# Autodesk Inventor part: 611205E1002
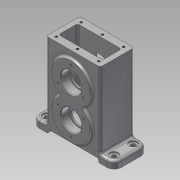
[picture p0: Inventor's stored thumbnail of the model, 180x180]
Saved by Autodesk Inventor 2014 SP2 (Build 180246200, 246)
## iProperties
Created: 2021-12
Part Number: 611205E1002
Material: 강철
Document SubType Name: Modeling
Designer: 거성
Density: 7.85 g/cm^3
Appearance: 강철
Mass: 1730.84 g
Surface Area: 577.617 cm^2
Volume: 220.489 cm^3
Author: 거성
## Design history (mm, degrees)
sketch "스케치1"
  geometry: L1 (-56, -5)-(-35, -5); L2 (-35, -5)-(-35, 0); L3 (-35, 0)-(35, 0); L4 (35, 0)-(35, -5); L5 (35, -5)-(56, -5); L6 (-56, -5)-(-56, 5); L7 (-56, 5)-(-37, 5); L8 (-37, 5)-(-37, 109); L9 (-37, 109)-(37, 109); L10 (37, 109)-(37, 5); L11 (37, 5)-(56, 5); L12 (56, 5)-(56, -5); 3 further points
  constraints: 24 end point, 6 parallel, 3 perpendicular, 2 collinear, 2 midpoint, 1 coincident, 1 horizontal, 1 horizontal alignment, 1 vertical alignment
  dimensions: "d0" = 112 distance between parallel lines of L12 L6; "d1" = 70 distance of L2.end L3.end; "d2" = 10 distance between parallel lines of L1 L7; "d3" = 10 distance between parallel lines of L11 L5; "d4" = 114 distance between parallel lines of L9 L5; "d5" = 5 distance of L1.end L2.end; "d6" = 21 distance of L1.start L1.end; "d7" = 74 distance between parallel lines of L10 L8
extrude "돌출1" new body sketch "스케치1" stored distance "d8" = 46; taper "d9" = 0 deg
sketch "스케치2"
  geometry: L1 (109, -23)-(0, -23) reference; L2 (0, -23)-(0, 23) reference; L3 (0, 23)-(109, 23) reference; L4 (109, 23)-(109, -23) reference; L5 (8, 13)-(109, 13); L6 (109, 13)-(109, -13); L7 (109, -13)-(8, -13); L8 (8, -13)-(8, 13); 3 further points
  constraints: 8 end point, 2 midpoint, 2 parallel, 1 coincident, 1 horizontal, 1 perpendicular
  dimensions: "d10" = 26 distance between parallel lines of L5 L7; "d11" = 10 distance between parallel lines of L1 L7; "d12" = 8 distance between parallel lines of L2 L8
extrude "돌출2" cut sketch "스케치2" stored distance "d13" = 60; taper "d14" = 0 deg
sketch "스케치3"
  geometry: L1 (-35, 0)-(35, 0) reference; L2 (35, -5)-(56, -5) reference; C1 r 26 at (0, 74); C2 r 26 at (0, 29); 4 further points
  constraints: 3 midpoint, 2 centre point, 2 vertical alignment
  dimensions: "d15" = 34 distance from line of C2.centre L2; "d16" = 79 distance from line of C1.centre L2; "d17" = 52 diameter of C1; "d18" = 52 diameter of C2
extrude "돌출3" join sketch "스케치3" distance "d19" = 3; taper "d20" = 0 deg
sketch "스케치4"
  geometry: C1 r 12 at (0, 74); C2 r 14 at (0, 74); C3 r 12 at (0, 29); C4 r 14 at (0, 29); A1 r 26 centre (0, 74) between (13.029, 51.5) and (-13.029, 51.5) reference; A2 r 26 centre (0, 29) between (-13.029, 51.5) and (13.029, 51.5) reference; 1 further point
  constraints: 4 centre point, 4 coincident
  dimensions: "d21" = 28 diameter of C2; "d22" = 24 diameter of C1; "d23" = 28 diameter of C4; "d24" = 24 diameter of C3
extrude "돌출4" cut sketch "스케치4" stored distance "d25" = 3; taper "d26" = 0 deg
extrude "돌출5" cut sketch "스케치4" distance "d27" = 11; taper "d28" = 0 deg
sketch "스케치5"
  geometry: C1 r 12 at (0, 74) reference; C2 r 12 at (0, 29) reference; C3 r 26 at (0, 74); C4 r 26 at (0, 29); 1 further point
  constraints: 2 centre point, 2 coincident
  dimensions: "d29" = 52 diameter of C3; "d30" = 52 diameter of C4
extrude "돌출6" join sketch "스케치5" distance "d31" = 3; taper "d32" = 0 deg
sketch "스케치6"
  geometry: C1 r 12 at (0, 29) reference; C2 r 16 at (0, 74); C3 r 14 at (0, 29); C4 r 14 at (0, 74); A1 r 26 centre (0, 74) between (13.029, 51.5) and (-13.029, 51.5) reference; A2 r 26 centre (0, 29) between (-13.029, 51.5) and (13.029, 51.5) reference; 1 further point
  constraints: 3 centre point, 3 coincident
  dimensions: "d33" = 28 diameter of C3; "d34" = 32 diameter of C2; "d35" = 28 diameter of C4
extrude "돌출7" cut sketch "스케치6" distance "d36" = 11; taper "d37" = 0 deg
extrude "돌출8" cut sketch "스케치6" distance "d38" = 20; taper "d39" = 0 deg
fillet "모깎기1" dims "d40" = 3, "d41" = 10
fillet "모깎기2" dims "d42" = 3
sketch "스케치7" dims "d43" = 40
  geometry: A1 r 26 centre (0, 74) between (16.403, 53.828) and (-16.403, 53.828) reference; 3 further points
  constraints: 2 vertical alignment, 1 coincident, 2 other
hole "구멍1" sketch "스케치7" at (0, 94) diameter "d44" = 3.242; stored, may be unused: countersink angle "d48" = 90 deg, drill point angle "d50" = 118 deg; dims "d45" = 8, "d46" = 4, "d47" = 2, "d49" = 10
sketch "스케치8" dims "d54" = 40
  geometry: C1 r 14 at (0, 29) reference; A1 r 26 centre (0, 29) between (-16.403, 49.172) and (16.403, 49.172) reference; 3 further points
  constraints: 2 vertical alignment, 1 coincident, 2 other
hole "구멍2" sketch "스케치8" at (0, 9) diameter "d55" = 3.242; stored, may be unused: countersink angle "d59" = 90 deg, drill point angle "d61" = 118 deg; dims "d56" = 8, "d57" = 4, "d58" = 2, "d60" = 10
sketch "스케치9" dims "d65" = 40, "d66" = 40
  geometry: C1 r 16 at (0, 74) reference; C2 r 14 at (0, 29) reference; A1 r 26 centre (0, 29) between (-16.403, 49.172) and (16.403, 49.172) reference; 5 further points
  constraints: 4 vertical alignment, 2 coincident, 4 other
hole "구멍3" sketch "스케치9" diameter "d67" = 3.242; stored, may be unused: countersink angle "d71" = 90 deg, drill point angle "d73" = 118 deg; dims "d68" = 8, "d69" = 4, "d70" = 2, "d72" = 10
hole "구멍4" sketch "스케치9" diameter "d77" = 3.242; stored, may be unused: countersink angle "d81" = 90 deg, drill point angle "d83" = 118 deg; dims "d78" = 8, "d79" = 4, "d80" = 2, "d82" = 10
sketch "스케치10"
  geometry: L1 (0, 0)-(68, 0) reference; L2 (-3, -3)-(-3, -43) reference; L3 (68, -46)-(0, -46) reference; L4 (71, -3)-(71, -43) reference; 7 further points
  constraints: 4 horizontal alignment, 4 vertical alignment
  dimensions: "d87" = 6 distance from line of L1 point (5, -6); "d88" = 8 distance from line of L2 point (5, -6); "d89" = 6 distance from line of L3 point (5, -40); "d90" = 8 distance from line of L4 point (63, -6)
hole "구멍5" sketch "스케치10" at (5, -6), (34, -6), (63, -6), (63, -40), (34, -40), (5, -40) diameter "d91" = 3.242; stored, may be unused: countersink angle "d95" = 90 deg, drill point angle "d97" = 118 deg; dims "d92" = 8, "d93" = 4, "d94" = 2, "d96" = 10
sketch "스케치11"
  geometry: 2 further points
  constraints: 1 coincident
hole "구멍6" sketch "스케치11" at (-32, 23) diameter "d98" = 4.917; stored, may be unused: countersink angle "d102" = 90 deg, drill point angle "d104" = 118 deg; dims "d99" = 8, "d100" = 11, "d101" = 1, "d103" = 20
sketch "스케치12"
  geometry: L1 (-56.279, -43)-(-74.804, -43) reference; L2 (-80, -40)-(-86, -40) reference; L3 (-93, -7)-(-93, -33) reference; L4 (-86, 0)-(-80, 0) reference; L5 (-80, -40)-(-80, 0) reference; L6 (-30, -46)-(-50, -46) reference; L7 (-5.196, -43)-(-23.721, -43) reference; L8 (0, -40)-(0, 0) reference; L9 (-23.721, 3)-(-5.196, 3) reference; L10 (-50, 6)-(-30, 6) reference; L11 (-74.804, 3)-(-56.279, 3) reference; L12 (6, -40)-(0, -40) reference; L13 (13, -7)-(13, -33) reference; L14 (0, 0)-(6, 0) reference; C1 r 2.458 at (-40, -20) reference; A1 r 7 centre (-86, -33) between (-93, -33) and (-86, -40) reference; A2 r 7 centre (-86, -7) between (-86, 0) and (-93, -7) reference; A3 r 7 centre (6, -33) between (6, -40) and (13, -33) reference; A4 r 7 centre (6, -7) between (13, -7) and (6, 0) reference; 5 further points
  constraints: 4 coincident, 8 other
hole "구멍7" sketch "스케치12" at (-86, -7), (-86, -33), (6, -33), (6, -7) diameter "d105" = 6.6; stored, may be unused: countersink angle "d109" = 90 deg, drill point angle "d111" = 118 deg; dims "d106" = 8, "d107" = 11, "d108" = 2, "d110" = 20
fillet "모깎기3" dims "d112" = 0.3
chamfer "모따기1" distance "d113" = 1; stored, may be unused: second distance "d114" = 2, angle "d115" = 45 deg
node "솔리드1"
pattern_circular "원형 패턴1" dims angle "d52" = 360 deg
pattern_circular "원형 패턴2" dims angle "d63" = 360 deg
pattern_circular "원형 패턴3" dims angle "d75" = 360 deg
pattern_circular "원형 패턴4" dims angle "d85" = 360 deg
node "절단 모서리 투영1"
node "절단 모서리 투영2"
